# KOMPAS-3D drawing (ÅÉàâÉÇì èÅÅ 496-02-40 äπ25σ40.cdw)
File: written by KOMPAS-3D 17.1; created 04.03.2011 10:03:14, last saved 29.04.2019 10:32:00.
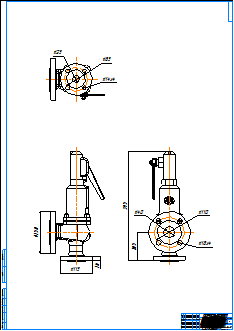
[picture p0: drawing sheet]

Sheet 1: A0, portrait

Title block, sheet 1: name: ПРЕГРАН КПП 496-02-40 / Ду25х40; material: Внимание! Данный продукт является объектом авторского права ООО «Торговый Дом АДЛ». / Запрещается изменение, копирование, распространение / (в том числе путем копирования на другие сайты и ресурсы в Интернете) / или любое иное использование информации и объектов без предварительного / согласия правообладателя (ООО «Торговый Дом АДЛ»).; scale: 1:1; sheets: 1; organisation: ООО "Торговый дом АДЛ"; sheet format: A0; stored path: C:\Users\tra\Desktop\2д чертежи\Предохранительные клапаны ПРЕГРАН\ПРЕГРАН 496\ПРЕГРАН КПП 496-02-40\KOMPAS 2D\ПРЕГРАН КПП 496-02-40 Ду25х40.cdw

Views: Спереди 1, Проекционный вид 2, Проекционный вид 3
Dimensions and other numbers on the sheet: 105; 115; 150; 110; 18; 16; 40; 85; 25; 14; 395; 1:1; 1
